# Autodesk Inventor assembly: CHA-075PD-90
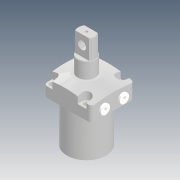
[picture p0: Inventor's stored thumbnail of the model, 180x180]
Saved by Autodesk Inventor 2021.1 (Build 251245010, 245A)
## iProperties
Created: 2018-11
Part Number: CHA-075PD-90
Description: STEP AP214
Document SubType Name: Assembly
Designer: user
Title: CHA-075PD-90.STEP
Revision Number: ÈÎºÎ
Sending System: SolidWorks 2016
Preprocessor: SwSTEP 2.0
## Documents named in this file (4)
- D:\Vault_2016\Projekty\Clamptek\Hydraulic\CHA-P\Inventor\CHA-075PD-90\CHA-075PD-90.iam
- D:\Vault_2016\Projekty\Clamptek\Hydraulic\CHA-P\Inventor\CHA-075PD-90\CHA-075P(BT).ipt
- D:\Vault_2016\Projekty\Clamptek\Hydraulic\CHA-P\Inventor\CHA-075PD-90\¶ÂÍ·G4-1.ipt
- D:\Vault_2016\Projekty\Clamptek\Hydraulic\CHA-P\Inventor\CHA-075PD-90\CHA-075PD(HSG) - ¸±±¾.ipt
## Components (4 placed, 4 different names)
1. CHA-075P(BT)_1
2. ¶ÂÍ·G4-1_2
3. ¶ÂÍ·G4-1_3
4. CHA-075PD(HSG) - ¸±±¾_4
